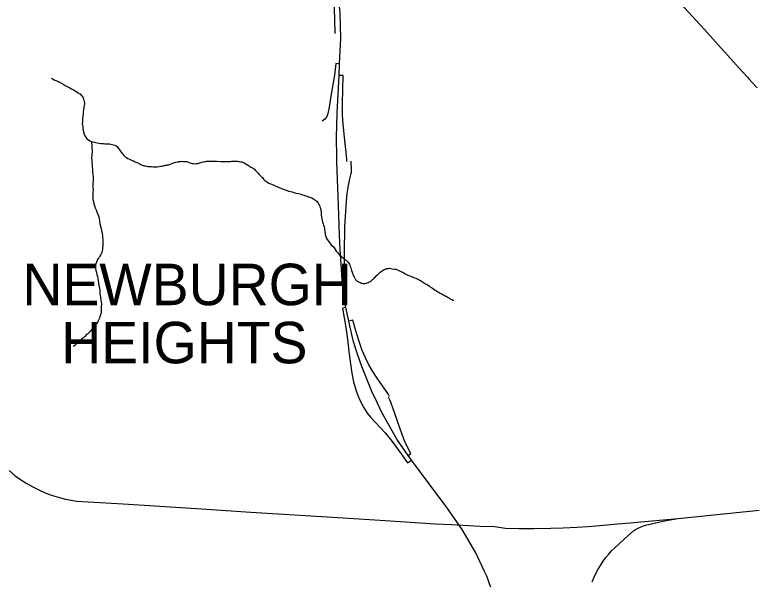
# Model space of a CAD drawing. Extents: x 0 to 96.2, y -27.5 to 31.3.
# Drawn here: x 47.23 to 48.919, y 14.924 to 16.212 of the extents above; entities that cross this region are included whole.
import ezdxf

# ---------------------------------------------------------------- set-up
doc = ezdxf.new("R2010")
doc.units = 0
for name, color, linetype in [('TB_BORDER', 7, 'Continuous'), ('TB_PP_50x10', 7, 'Continuous'), ('TB_PP_50x10_GRID', 7, 'Continuous'), ('TB_PROF_20x5_GRID', 7, 'Continuous'), ('TB_PSDSOD', 7, 'Continuous'), ('TB_PSNSUM', 7, 'Continuous')]:
    doc.layers.add(name, color=color, linetype=linetype)

msp = doc.modelspace()

# ---------------------------------------------------------------- linework, layer by layer
at = {"layer": 'TB_BORDER'}
for points in [[(47.3134, 16.0682), (47.3142, 16.0667), (47.3172, 16.0652), (47.3214, 16.0633), (47.326, 16.0615), (47.3306, 16.0593), (47.3352, 16.0567), (47.3398, 16.0537), (47.3448, 16.0507), (47.3509, 16.0481), (47.3551, 16.0455), (47.3593, 16.0429), (47.3635, 16.0407), (47.3677, 16.0384), (47.3712, 16.0362), (47.3742, 16.034), (47.3769, 16.0325), (47.3788, 16.0314), (47.3815, 16.0291), (47.3835, 16.0269), (47.3846, 16.025), (47.3858, 16.0223), (47.3866, 16.0197), (47.3874, 16.017), (47.3882, 16.0144), (47.3886, 16.0117), (47.3886, 16.0087), (47.3883, 16.0049), (47.3876, 16.0003), (47.3869, 15.9957), (47.3862, 15.99), (47.3855, 15.9858), (47.3848, 15.9809), (47.3845, 15.9759), (47.3842, 15.9714), (47.3843, 15.9672), (47.3839, 15.9638), (47.3844, 15.9604), (47.3848, 15.9566), (47.3852, 15.9524), (47.3857, 15.9486), (47.3865, 15.9448), (47.3881, 15.9399), (47.3893, 15.9361), (47.3916, 15.9327), (47.3943, 15.9293), (47.3977, 15.9267), (47.4012, 15.9248), (47.4046, 15.923), (47.4149, 15.9205), (47.418, 15.9197), (47.4214, 15.919), (47.4259, 15.9187), (47.429, 15.9183), (47.432, 15.9184), (47.4354, 15.918), (47.4392, 15.9177), (47.4427, 15.9177), (47.4461, 15.9174), (47.4491, 15.9171), (47.4522, 15.9163), (47.4552, 15.9156), (47.4579, 15.9145), (47.461, 15.913), (47.4636, 15.9112), (47.4648, 15.9093), (47.4667, 15.907), (47.4687, 15.904), (47.4706, 15.9014), (47.4725, 15.8987), (47.4745, 15.8961), (47.4768, 15.8938), (47.4791, 15.8908), (47.4818, 15.8882), (47.4852, 15.8863), (47.4883, 15.8845), (47.4917, 15.8826), (47.4948, 15.8811), (47.4979, 15.8796), (47.5009, 15.8785), (47.5044, 15.8767), (47.5086, 15.8748), (47.5124, 15.8734), (47.5154, 15.8719), (47.5177, 15.8708), (47.5208, 15.8693), (47.5231, 15.8682), (47.5257, 15.8674), (47.528, 15.8671), (47.5315, 15.8664), (47.5334, 15.866), (47.536, 15.866), (47.5391, 15.8657), (47.5421, 15.8657), (47.5459, 15.8654), (47.5482, 15.8654), (47.5516, 15.8651), (47.555, 15.8655), (47.5592, 15.8659), (47.5626, 15.8664), (47.5649, 15.8668)], [(47.4046, 15.923), (47.4061, 15.9002), (47.4054, 15.8926), (47.4051, 15.8858), (47.4056, 15.8804), (47.4066, 15.8652), (47.407, 15.8592), (47.4075, 15.8531), (47.4079, 15.8474), (47.4084, 15.8428), (47.4084, 15.8379), (47.4085, 15.833), (47.4082, 15.828), (47.4083, 15.8231), (47.4083, 15.8178), (47.4084, 15.8128), (47.4081, 15.8067), (47.4078, 15.8022), (47.4078, 15.7988), (47.4079, 15.7946), (47.4083, 15.7904), (47.4092, 15.7859), (47.41, 15.7809), (47.4116, 15.776), (47.4135, 15.7715), (47.4155, 15.7669), (47.4171, 15.7624), (47.419, 15.7586), (47.421, 15.7529), (47.4222, 15.7476), (47.4231, 15.7416), (47.4243, 15.7351), (47.4255, 15.7298), (47.4271, 15.7245), (47.4279, 15.72), (47.4287, 15.7162), (47.4295, 15.712), (47.43, 15.7082), (47.43, 15.7044), (47.4305, 15.6998), (47.4305, 15.696), (47.431, 15.6911), (47.4307, 15.6854), (47.4304, 15.6805), (47.43, 15.6767), (47.4293, 15.6736), (47.429, 15.6709), (47.4275, 15.6683), (47.426, 15.6648), (47.4242, 15.661), (47.4223, 15.6579), (47.4204, 15.6556), (47.419, 15.6533), (47.416, 15.6476), (47.4145, 15.6438), (47.4142, 15.6411), (47.4142, 15.6377), (47.4143, 15.6328), (47.4151, 15.6286), (47.4163, 15.6241), (47.4171, 15.6195), (47.4183, 15.615), (47.4192, 15.61), (47.42, 15.6047), (47.4208, 15.5994), (47.422, 15.5945), (47.4229, 15.5892), (47.4237, 15.5827), (47.4242, 15.5759), (47.4254, 15.5679), (47.4263, 15.5618), (47.4271, 15.5569), (47.4276, 15.5527), (47.4276, 15.5501), (47.4272, 15.5474), (47.4273, 15.5451), (47.4273, 15.5421), (47.427, 15.5391), (47.427, 15.536), (47.4267, 15.5333), (47.4263, 15.5299), (47.4256, 15.5273), (47.4249, 15.525), (47.4242, 15.5227), (47.4231, 15.52), (47.422, 15.5169), (47.4205, 15.5135), (47.4183, 15.5097), (47.416, 15.507), (47.4142, 15.5043), (47.4116, 15.5005), (47.4086, 15.4966), (47.4045, 15.4924), (47.4018, 15.4893), (47.3992, 15.4863), (47.3966, 15.484), (47.3943, 15.4824), (47.3921, 15.4805), (47.3895, 15.4778), (47.3865, 15.4751), (47.3831, 15.4724)], [(47.5649, 15.8668), (47.5679, 15.8676), (47.5702, 15.8676), (47.5721, 15.868), (47.5743, 15.8688), (47.577, 15.8692), (47.5789, 15.8696), (47.5811, 15.87), (47.5834, 15.8708), (47.5868, 15.872), (47.5887, 15.8728), (47.5906, 15.8732), (47.5932, 15.8743), (47.5951, 15.8747), (47.5978, 15.8759), (47.6012, 15.8763), (47.6035, 15.8767), (47.6053, 15.8771), (47.6076, 15.8776), (47.6099, 15.8776), (47.6118, 15.878), (47.6145, 15.8776), (47.6198, 15.8773), (47.6228, 15.877), (47.6266, 15.8755), (47.6297, 15.8744), (47.6327, 15.8733), (47.635, 15.8729), (47.6381, 15.8726), (47.6407, 15.8723), (47.6441, 15.8727), (47.646, 15.8727), (47.6483, 15.8731), (47.6502, 15.8735), (47.6525, 15.8743), (47.6551, 15.8747), (47.6578, 15.8755), (47.66, 15.8763), (47.6638, 15.8775), (47.6661, 15.8775), (47.668, 15.8779), (47.6699, 15.8779), (47.6729, 15.8783), (47.6915, 15.8782), (47.7006, 15.8775), (47.7109, 15.8773), (47.7151, 15.8773), (47.7181, 15.8774), (47.7215, 15.8774), (47.7249, 15.8778), (47.7284, 15.8779), (47.7318, 15.8779), (47.7352, 15.878), (47.7386, 15.878), (47.7413, 15.8776), (47.7432, 15.8773), (47.7462, 15.8769), (47.7485, 15.8762), (47.7512, 15.8751), (47.7538, 15.874), (47.7573, 15.8721), (47.7607, 15.8699), (47.7649, 15.8673), (47.7692, 15.8647), (47.7726, 15.8628), (47.7753, 15.861), (47.7772, 15.8595), (47.7791, 15.8572), (47.7814, 15.855), (47.7837, 15.8531), (47.7861, 15.8504), (47.7876, 15.8486), (47.7895, 15.8463), (47.7915, 15.8441), (47.7934, 15.8422), (47.7953, 15.8407), (47.798, 15.8373), (47.7996, 15.8354), (47.8019, 15.8335), (47.8042, 15.8317), (47.8072, 15.8298), (47.8103, 15.8279), (47.8141, 15.8261), (47.8198, 15.8239), (47.8248, 15.8217), (47.8431, 15.8139), (47.8496, 15.8117), (47.855, 15.8099), (47.8595, 15.8088), (47.8637, 15.8077), (47.8675, 15.8066), (47.8717, 15.8051), (47.8771, 15.8044), (47.8809, 15.8033), (47.8839, 15.8026), (47.8874, 15.8015), (47.8908, 15.8004), (47.8942, 15.7989), (47.8977, 15.7978), (47.9011, 15.7967), (47.9038, 15.796)], [(47.9038, 15.796), (47.906, 15.7953), (47.908, 15.7942), (47.9103, 15.7927), (47.9129, 15.7916), (47.9152, 15.7901), (47.9175, 15.7886), (47.9194, 15.7867), (47.9214, 15.7844), (47.9229, 15.7822), (47.9241, 15.7795), (47.9257, 15.7769), (47.9268, 15.7742), (47.9276, 15.772), (47.9284, 15.7697), (47.9292, 15.7663), (47.9296, 15.764), (47.9297, 15.7614), (47.9297, 15.7583), (47.9298, 15.7545), (47.9302, 15.75), (47.931, 15.7465), (47.9318, 15.7428), (47.933, 15.7386), (47.9342, 15.7348), (47.935, 15.7318), (47.9362, 15.7284), (47.937, 15.7253), (47.9374, 15.7219), (47.9378, 15.7189), (47.9383, 15.7162), (47.9387, 15.714), (47.9391, 15.7109), (47.9415, 15.7015), (47.9477, 15.6928), (47.9527, 15.6871), (47.9569, 15.6834), (47.9593, 15.68), (47.962, 15.6762), (47.9643, 15.6725), (47.9674, 15.6687), (47.9709, 15.6649), (47.9743, 15.6616), (47.9774, 15.6589), (47.9805, 15.6563), (47.9835, 15.6537), (47.987, 15.6518), (47.9893, 15.6496), (47.9916, 15.6473), (47.9931, 15.6455), (47.9943, 15.6432), (47.9955, 15.6405), (47.9963, 15.6379), (47.9971, 15.6349), (47.9983, 15.6318), (47.9991, 15.6284), (48.0003, 15.625), (48.0018, 15.6201), (48.003, 15.6167), (48.005, 15.6137), (48.0065, 15.611), (48.0085, 15.6076), (48.0112, 15.605), (48.0139, 15.6031), (48.0165, 15.602), (48.0192, 15.6009), (48.0219, 15.5998), (48.0257, 15.5991), (48.0291, 15.5988), (48.0325, 15.5992), (48.0348, 15.6), (48.037, 15.6008), (48.0397, 15.6023), (48.0423, 15.6035), (48.0442, 15.6046), (48.0465, 15.607), (48.0491, 15.6089), (48.0509, 15.6116), (48.0536, 15.6143), (48.0562, 15.617), (48.0596, 15.62), (48.0622, 15.6223), (48.0648, 15.6247), (48.0735, 15.6305), (48.0769, 15.6316), (48.0799, 15.6328), (48.0833, 15.6332), (48.086, 15.6337), (48.0886, 15.6333), (48.092, 15.6326), (48.097, 15.6319), (48.1004, 15.6312), (48.1038, 15.6301), (48.1069, 15.6286), (48.11, 15.6271), (48.113, 15.6256), (48.1161, 15.6245), (48.1188, 15.623), (48.1218, 15.6212), (48.1249, 15.6197), (48.1279, 15.6182)], [(48.1279, 15.6182), (48.1325, 15.616), (48.1363, 15.6145), (48.1409, 15.6127), (48.1459, 15.6112), (48.1508, 15.609), (48.155, 15.6067), (48.1593, 15.6041), (48.1635, 15.6011), (48.1681, 15.5982), (48.1723, 15.5956), (48.1761, 15.5933), (48.1796, 15.5903), (48.1842, 15.5881), (48.1872, 15.5859), (48.1903, 15.5836), (48.1934, 15.5817), (48.1964, 15.5799), (48.1995, 15.578), (48.2018, 15.5769), (48.2041, 15.5758), (48.206, 15.5743), (48.2083, 15.5732), (48.211, 15.5721), (48.2144, 15.5698), (48.2175, 15.5684), (48.2201, 15.5665), (48.2228, 15.565), (48.2255, 15.5631), (48.2286, 15.562), (48.2305, 15.5609), (48.232, 15.5606), (48.2328, 15.5602)], [(47.3831, 15.4724), (47.3797, 15.4693), (47.3666, 15.457), (47.3643, 15.4558), (47.3636, 15.4554), (47.3632, 15.4554)]]:
    msp.add_lwpolyline(points, dxfattribs=at)
at = {"layer": 'TB_PP_50x10_GRID'}
for points in [[(47.8919, 16.3721), (47.9161, 16.3523), (47.9364, 16.3349), (47.9412, 16.3293), (47.9446, 16.3232), (47.9474, 16.3152), (47.9541, 16.2766), (47.9561, 16.2588), (47.959, 16.226), (47.9603, 16.2004), (47.9606, 16.1697)], [(47.2167, 15.1723), (47.2301, 15.1609), (47.2404, 15.153), (47.2573, 15.1422), (47.2707, 15.1347), (47.2861, 15.1267), (47.3004, 15.1204), (47.3161, 15.1146), (47.3316, 15.11), (47.3456, 15.1068), (47.3588, 15.1043), (47.3717, 15.1023), (47.397, 15.1007), (47.4775, 15.0956), (47.6446, 15.0851), (47.7693, 15.0772), (47.9433, 15.0664), (48.0645, 15.0585), (48.1904, 15.0505), (48.2273, 15.0488), (48.2933, 15.0447), (48.3259, 15.0438), (48.3509, 15.0405), (48.3812, 15.0397), (48.4155, 15.0398), (48.4545, 15.0403), (48.4826, 15.0412), (48.5136, 15.0425), (48.5391, 15.0442), (48.5663, 15.0465), (48.6065, 15.0499), (48.6358, 15.0521), (48.7111, 15.0591), (48.7452, 15.062)], [(48.7452, 15.062), (48.9304, 15.0814)], [(48.5491, 14.9181), (48.5529, 14.9271), (48.5576, 14.937), (48.5628, 14.9467), (48.568, 14.9552), (48.5743, 14.9646), (48.5803, 14.9731), (48.5868, 14.9813), (48.5928, 14.9882), (48.6011, 14.9961), (48.6307, 15.0229), (48.6432, 15.0341), (48.6479, 15.0376), (48.6552, 15.0413), (48.6626, 15.0442), (48.6707, 15.0468), (48.7178, 15.0577), (48.7452, 15.062)]]:
    msp.add_lwpolyline(points, dxfattribs=at)
at = {"layer": 'TB_PROF_20x5_GRID'}
for points in [[(47.9719, 16.1006), (47.9634, 16.101), (47.9599, 16.0743), (47.9519, 16.0265), (47.9474, 15.9968), (47.9444, 15.9836), (47.9421, 15.9783), (47.9383, 15.9739), (47.9323, 15.9694)], [(47.9883, 15.8776), (47.9881, 15.8832), (47.9821, 15.9395), (47.98, 15.9631), (47.9784, 15.9831), (47.9783, 16.0095), (47.98, 16.0735), (47.9705, 16.0739)], [(47.9758, 15.6305), (47.9831, 15.6309), (47.983, 15.6691), (47.9841, 15.7278), (47.9877, 15.7868), (47.9893, 15.8045), (47.9923, 15.8228), (47.995, 15.8375), (47.9985, 15.8502), (47.9988, 15.8524), (47.9989, 15.8547), (47.999, 15.8624), (47.9985, 15.8733), (47.9983, 15.878)], [(47.9858, 15.5443), (47.9784, 15.5427), (47.9862, 15.4982), (47.989, 15.4768), (47.994, 15.4385), (47.997, 15.4151), (47.9997, 15.3942), (48.0036, 15.374), (48.0095, 15.3539), (48.0153, 15.3391), (48.0258, 15.3175), (48.0303, 15.3104)], [(48.0857, 15.3407), (48.0828, 15.3467), (48.0696, 15.3649), (48.0578, 15.3824), (48.0474, 15.3979), (48.0378, 15.4146), (48.0307, 15.4294), (48.0236, 15.4462), (48.0163, 15.4661), (48.0089, 15.4911), (48.0023, 15.5149), (47.9928, 15.5128)], [(48.1284, 15.2065), (48.1347, 15.2109), (48.1269, 15.2254), (48.1208, 15.2385), (48.1157, 15.2522), (48.0889, 15.3279), (48.0862, 15.3336), (48.0833, 15.3396)], [(48.0303, 15.3104), (48.035, 15.3029), (48.0434, 15.2926), (48.0761, 15.2578), (48.0917, 15.2379), (48.1123, 15.2098), (48.1273, 15.1891), (48.1361, 15.1952)]]:
    msp.add_lwpolyline(points, dxfattribs=at)
at = {"layer": 'TB_PSDSOD'}
msp.add_lwpolyline([(48.7504, 16.2398), (48.7601, 16.2283), (48.8058, 16.1783), (48.8369, 16.1434), (48.8649, 16.1125), (48.8914, 16.0829), (48.9042, 16.0688), (48.9067, 16.0661), (48.9233, 16.0479), (48.9256, 16.0453)], dxfattribs=at)
at = {"layer": 'TB_PSNSUM'}
for points in [[(47.9654, 15.8864), (47.9646, 15.9318), (47.9661, 15.9879), (47.9705, 16.0739), (47.9719, 16.1006), (47.9744, 16.1584), (47.9728, 16.2161), (47.9672, 16.2788), (47.9487, 16.3975), (47.9329, 16.4985), (47.9188, 16.5651), (47.9018, 16.6213), (47.856, 16.7413), (47.8491, 16.7626), (47.8424, 16.7832), (47.8333, 16.8191), (47.8256, 16.8683), (47.8214, 16.9124), (47.8172, 16.9518)], [(47.9719, 15.7092), (47.9696, 15.7765), (47.9655, 15.8765), (47.9654, 15.8864)], [(48.0712, 15.2993), (48.07, 15.3013), (48.0573, 15.3274), (48.0452, 15.3523), (48.0224, 15.4092), (48.0129, 15.4373), (48.0038, 15.4658), (47.9958, 15.4992), (47.9928, 15.5128), (47.9858, 15.5443), (47.9773, 15.6061), (47.9758, 15.6305), (47.973, 15.6768), (47.9719, 15.7092)], [(48.3023, 14.9426), (48.2831, 14.9839), (48.2519, 15.037), (48.2167, 15.0878), (48.1361, 15.1952), (48.1284, 15.2065), (48.1029, 15.2437), (48.0712, 15.2993)], [(48.3296, 14.8714), (48.3173, 14.905), (48.3079, 14.9304), (48.3023, 14.9426)]]:
    msp.add_lwpolyline(points, dxfattribs=at)

# ---------------------------------------------------------------- texts
at = {"layer": 'TB_PP_50x10'}
for s, p in [('NEWBURGH', (47.2469, 15.5493)), ('HEIGHTS', (47.3356, 15.4166))]:
    msp.add_text(s, height=0.0947, rotation=0, dxfattribs=at).set_placement(p)

doc.saveas('drawing.dxf')
